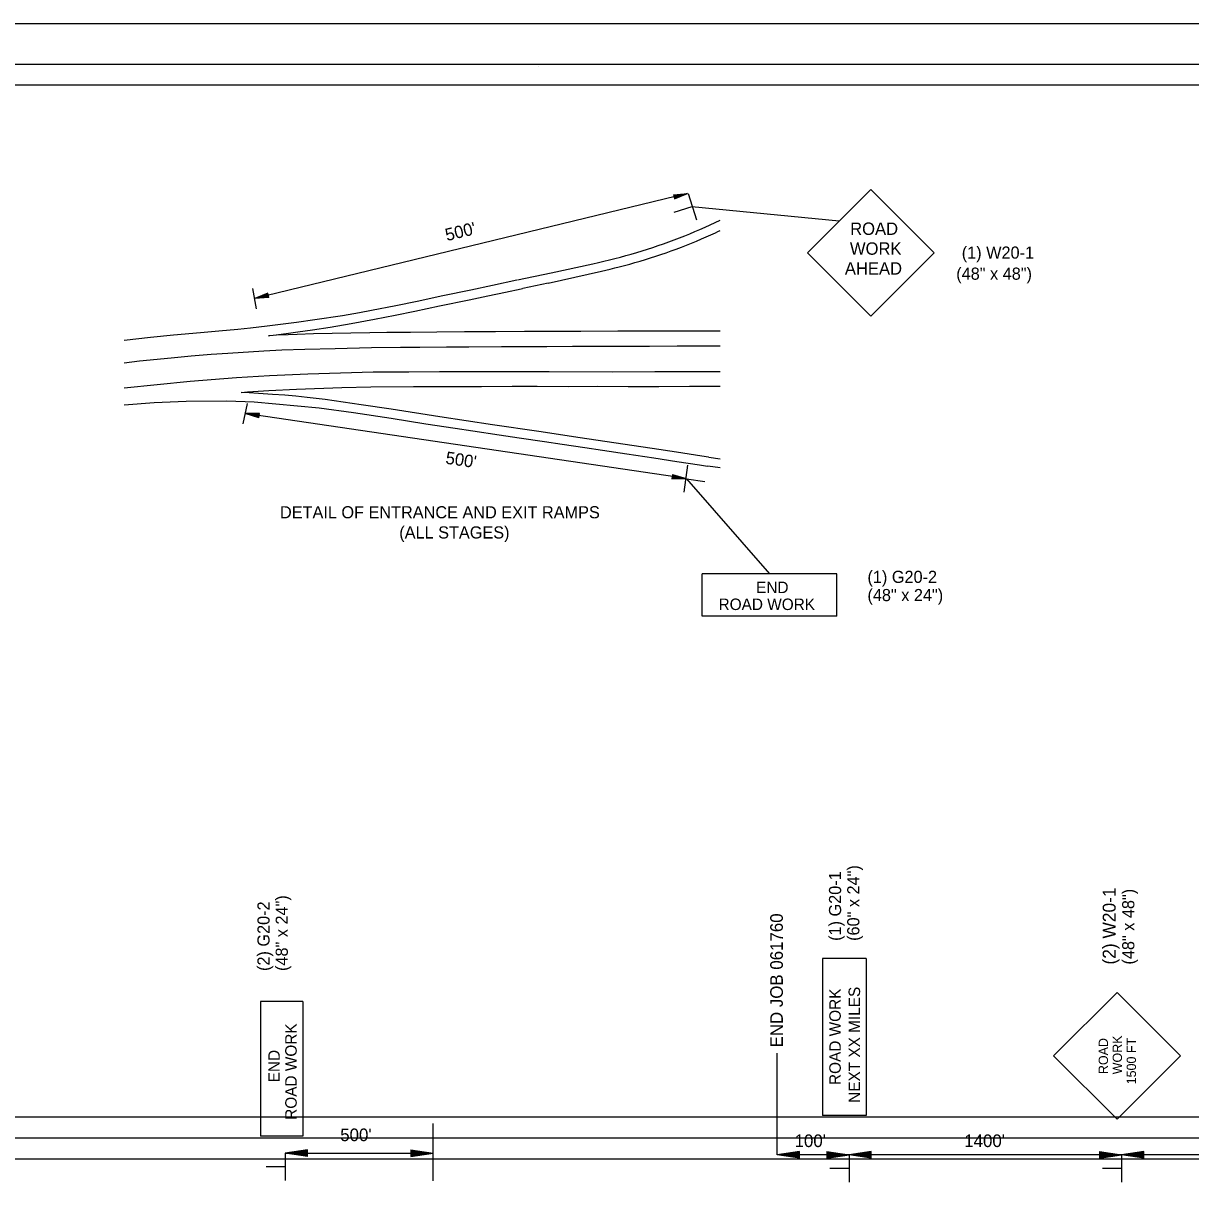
# Model space of a CAD drawing. Extents: x -500 to 213, y 382723 to 382830.
# Drawn here: x -442.4 to -386.5, y 382774.3 to 382829.8 of the extents above; entities that cross this region are included whole.
import ezdxf

# ---------------------------------------------------------------- set-up
doc = ezdxf.new("R2010")
doc.units = 0
for name, color, linetype in [('Default', 7, 'Continuous'), ('R_Border', 7, 'Continuous'), ('R_Border Plan-Plan', 7, 'Continuous'), ('R_Detour', 7, 'Continuous'), ('R_Draft', 7, 'Continuous'), ('R_MOT', 7, 'Continuous'), ('R_No Plot', 7, 'Continuous')]:
    doc.layers.add(name, color=color, linetype=linetype)

msp = doc.modelspace()

# ---------------------------------------------------------------- linework, layer by layer
at = {"layer": 'Default'}
for p, q in [((-403.358, 382820.332), (-410.403, 382821.028)), ((-410.66, 382808.014), (-406.683, 382803.472)), ((-406.313, 382775.68), (-406.313, 382780.536)), ((-422.773, 382774.434), (-422.773, 382777.171)), ((-429.838, 382775.757), (-422.775, 382775.757)), ((-402.883, 382775.68), (-406.313, 382775.68)), ((-389.854, 382775.68), (-402.883, 382775.68)), ((-380.757, 382775.68), (-389.854, 382775.68))]:
    msp.add_line(p, q, dxfattribs=at)
for points in [[(-418.736, 382817.53), (-417.12, 382817.87), (-415.135, 382818.302)], [(-437.544, 382814.647), (-436.29, 382814.788), (-435.182, 382814.895), (-433.892, 382815.008), (-433.019, 382815.086), (-432.105, 382815.177), (-431.51, 382815.241), (-430.701, 382815.334), (-429.298, 382815.51), (-428.426, 382815.627), (-427.104, 382815.83), (-426.289, 382815.968), (-425.71, 382816.081), (-424.552, 382816.304), (-423.533, 382816.517), (-422.3, 382816.774), (-420.965, 382817.054), (-419.937, 382817.276), (-418.765, 382817.522)], [(-417.273, 382817.376), (-418.476, 382817.122)], [(-409.045, 382815.08), (-409.589, 382815.08), (-411.228, 382815.075), (-412.482, 382815.072), (-413.933, 382815.07), (-415.709, 382815.063), (-417.031, 382815.059), (-418.402, 382815.056), (-419.784, 382815.048), (-421.276, 382815.035), (-422.597, 382815.029), (-423.847, 382815.015), (-424.985, 382815.004), (-425.8, 382814.997), (-426.699, 382814.984), (-427.598, 382814.968), (-428.49, 382814.942), (-429.267, 382814.916), (-429.695, 382814.899), (-430.268, 382814.876), (-430.571, 382814.858), (-430.646, 382814.857), (-430.577, 382814.868), (-430.276, 382814.903), (-429.691, 382814.978), (-429.243, 382815.037), (-428.537, 382815.141), (-427.693, 382815.271), (-426.692, 382815.434), (-425.567, 382815.642), (-424.593, 382815.835), (-423.65, 382816.033), (-422.468, 382816.282), (-421.049, 382816.579), (-420.156, 382816.765), (-419.316, 382816.942), (-418.558, 382817.103), (-418.501, 382817.119)], [(-437.544, 382813.563), (-436.816, 382813.648), (-435.302, 382813.802), (-434.342, 382813.895), (-433.377, 382813.971), (-432.592, 382814.027), (-430.87, 382814.136), (-430.005, 382814.174), (-428.905, 382814.211), (-427.457, 382814.251), (-425.721, 382814.287), (-424.327, 382814.305), (-423.408, 382814.312), (-422.136, 382814.321), (-421.058, 382814.328), (-419.507, 382814.335), (-418.42, 382814.34), (-417.332, 382814.346), (-416.108, 382814.351), (-414.413, 382814.356), (-412.427, 382814.361), (-411.101, 382814.366), (-409.647, 382814.368), (-409.045, 382814.368)], [(-437.544, 382812.368), (-434.386, 382812.678), (-432.18, 382812.851), (-430.589, 382812.951), (-428.76, 382813.036), (-425.632, 382813.122), (-423.934, 382813.136), (-422.459, 382813.143), (-419.938, 382813.141), (-417.224, 382813.14), (-414.198, 382813.135), (-412.168, 382813.138), (-410.511, 382813.142), (-409.045, 382813.143)], [(-409.597, 382809.05), (-409.93, 382809.102), (-411.14, 382809.286), (-412.298, 382809.463), (-414.126, 382809.735), (-415.733, 382809.973), (-417.719, 382810.273), (-419.928, 382810.596), (-422.443, 382810.982), (-424.781, 382811.348), (-426.219, 382811.554), (-427.939, 382811.811), (-428.788, 382811.907), (-429.334, 382811.96), (-429.863, 382812.006), (-430.45, 382812.051), (-431.569, 382812.122), (-431.946, 382812.141), (-431.951, 382812.148), (-431.64, 382812.175), (-430.621, 382812.235), (-429.309, 382812.299), (-427.133, 382812.386), (-425.754, 382812.413), (-423.702, 382812.424), (-422.078, 382812.424), (-420.464, 382812.427), (-418.991, 382812.436), (-417.798, 382812.437), (-416.314, 382812.434), (-414.934, 382812.436), (-413.442, 382812.43), (-411.975, 382812.429), (-410.509, 382812.436), (-409.218, 382812.437), (-409.045, 382812.438)], [(-437.544, 382811.547), (-436.115, 382811.669), (-434.58, 382811.733), (-432.628, 382811.744), (-431.322, 382811.702), (-428.216, 382811.41), (-426.584, 382811.179), (-424.777, 382810.906), (-423.117, 382810.648), (-421.714, 382810.434), (-420.878, 382810.303), (-419.614, 382810.11), (-418.651, 382809.975), (-417.453, 382809.796), (-416.593, 382809.667), (-415.523, 382809.507), (-414.68, 382809.38), (-413.515, 382809.202), (-412.224, 382809.01), (-411.111, 382808.843), (-410.038, 382808.68), (-409.659, 382808.624)], [(-409.586, 382809.048), (-409.045, 382808.965)], [(-409.045, 382808.53), (-409.642, 382808.619)]]:
    msp.add_lwpolyline(points, dxfattribs=at)
for centre, major_axis, ratio, start_param, end_param in [((-423.101, 382850.023), (13.67, 29.837), 0.999173, 3.949784, 4.014407), ((-422.295, 382848.064), (31.169, 0.376), 0.99865, 5.108014, 5.139342), ((-420.612, 382844.147), (26.163, 4.854), 0.992861, 4.737589, 4.90036), ((-420.215, 382843.153), (25.787, 2.344), 0.996093, 4.869476, 5.030314), ((-437.119, 382911.522), (96.683, 14.944), 0.983429, 4.765892, 4.801526)]:
    msp.add_ellipse(centre, major_axis=major_axis, ratio=ratio, start_param=start_param, end_param=end_param, dxfattribs=at)
at = {"layer": 'R_Border'}
for p, q in [((-493.998, 382827.85), (-335.908, 382827.85)), ((-417.738, 382827.72), (-417.738, 382827.72)), ((-417.738, 382827.72), (-417.738, 382827.72))]:
    msp.add_line(p, q, dxfattribs=at)
at = {"layer": 'R_Border Plan-Plan'}
msp.add_line((-493.998, 382776.485), (-335.908, 382776.485), dxfattribs=at)
at = {"layer": 'R_Detour'}
for p, q in [((-404.157, 382785.063), (-404.157, 382777.559)), ((-402.071, 382785.063), (-404.157, 382785.063)), ((-402.071, 382785.063), (-402.071, 382777.559)), ((-402.071, 382777.559), (-404.157, 382777.559))]:
    msp.add_line(p, q, dxfattribs=at)
at = {"layer": 'R_Draft'}
for p, q in [((-428.778, 382775.916), (-429.838, 382775.757)), ((-428.778, 382775.598), (-429.838, 382775.757)), ((-428.778, 382775.889), (-429.661, 382775.757)), ((-428.778, 382775.625), (-429.661, 382775.757)), ((-428.778, 382775.862), (-429.478, 382775.757)), ((-428.778, 382775.652), (-429.478, 382775.757)), ((-428.778, 382775.836), (-429.302, 382775.757)), ((-428.778, 382775.678), (-429.302, 382775.757)), ((-428.778, 382775.809), (-429.122, 382775.757)), ((-428.778, 382775.706), (-429.122, 382775.757)), ((-428.778, 382775.782), (-428.946, 382775.757)), ((-428.778, 382775.732), (-428.946, 382775.757)), ((-428.778, 382775.598), (-428.778, 382775.916)), ((-423.834, 382775.916), (-422.775, 382775.757)), ((-423.834, 382775.916), (-423.834, 382775.598)), ((-423.834, 382775.889), (-422.952, 382775.757)), ((-423.834, 382775.862), (-423.134, 382775.757)), ((-423.834, 382775.836), (-423.31, 382775.757)), ((-423.834, 382775.808), (-423.49, 382775.757)), ((-423.834, 382775.782), (-423.667, 382775.757)), ((-423.834, 382775.598), (-422.775, 382775.757)), ((-423.834, 382775.705), (-423.49, 382775.757)), ((-423.834, 382775.652), (-423.134, 382775.757)), ((-423.834, 382775.625), (-422.952, 382775.757)), ((-423.834, 382775.678), (-423.31, 382775.757)), ((-423.834, 382775.732), (-423.667, 382775.757)), ((-405.254, 382775.839), (-406.313, 382775.68)), ((-405.254, 382775.521), (-406.313, 382775.68)), ((-405.254, 382775.813), (-406.136, 382775.68)), ((-405.254, 382775.548), (-406.136, 382775.68)), ((-405.254, 382775.786), (-405.954, 382775.68)), ((-405.254, 382775.575), (-405.954, 382775.68)), ((-405.254, 382775.759), (-405.777, 382775.68)), ((-405.254, 382775.601), (-405.777, 382775.68)), ((-405.254, 382775.732), (-405.598, 382775.68)), ((-405.254, 382775.629), (-405.598, 382775.68)), ((-405.254, 382775.705), (-405.421, 382775.68)), ((-405.254, 382775.656), (-405.421, 382775.68)), ((-405.254, 382775.521), (-405.254, 382775.839)), ((-403.942, 382775.839), (-402.883, 382775.68)), ((-403.942, 382775.839), (-403.942, 382775.521)), ((-403.942, 382775.813), (-403.06, 382775.68)), ((-403.942, 382775.786), (-403.242, 382775.68)), ((-403.942, 382775.759), (-403.418, 382775.68)), ((-403.942, 382775.732), (-403.598, 382775.68)), ((-403.942, 382775.705), (-403.775, 382775.68)), ((-403.942, 382775.521), (-402.883, 382775.68)), ((-403.942, 382775.628), (-403.598, 382775.68)), ((-403.942, 382775.575), (-403.242, 382775.68)), ((-403.942, 382775.548), (-403.06, 382775.68)), ((-403.942, 382775.601), (-403.418, 382775.68)), ((-403.942, 382775.656), (-403.775, 382775.68)), ((-401.823, 382775.839), (-402.883, 382775.68)), ((-401.823, 382775.521), (-402.883, 382775.68)), ((-401.823, 382775.813), (-402.706, 382775.68)), ((-401.823, 382775.548), (-402.706, 382775.68)), ((-401.823, 382775.786), (-402.524, 382775.68)), ((-401.823, 382775.575), (-402.524, 382775.68)), ((-401.823, 382775.759), (-402.347, 382775.68)), ((-401.823, 382775.601), (-402.347, 382775.68)), ((-401.823, 382775.732), (-402.168, 382775.68)), ((-401.823, 382775.629), (-402.168, 382775.68)), ((-401.823, 382775.705), (-401.991, 382775.68)), ((-401.823, 382775.656), (-401.991, 382775.68)), ((-401.823, 382775.521), (-401.823, 382775.839)), ((-390.913, 382775.839), (-389.854, 382775.68)), ((-390.913, 382775.839), (-390.913, 382775.521)), ((-390.913, 382775.813), (-390.031, 382775.68)), ((-390.913, 382775.786), (-390.213, 382775.68)), ((-390.913, 382775.759), (-390.389, 382775.68)), ((-390.913, 382775.732), (-390.569, 382775.68)), ((-390.913, 382775.705), (-390.746, 382775.68)), ((-390.913, 382775.521), (-389.854, 382775.68)), ((-390.913, 382775.628), (-390.569, 382775.68)), ((-390.913, 382775.575), (-390.213, 382775.68)), ((-390.913, 382775.548), (-390.031, 382775.68)), ((-390.913, 382775.601), (-390.389, 382775.68)), ((-390.913, 382775.656), (-390.746, 382775.68)), ((-388.794, 382775.839), (-389.854, 382775.68)), ((-388.794, 382775.521), (-389.854, 382775.68)), ((-388.794, 382775.813), (-389.677, 382775.68)), ((-388.794, 382775.548), (-389.677, 382775.68)), ((-388.794, 382775.786), (-389.494, 382775.68)), ((-388.794, 382775.575), (-389.494, 382775.68)), ((-388.794, 382775.759), (-389.318, 382775.68)), ((-388.794, 382775.601), (-389.318, 382775.68)), ((-388.794, 382775.732), (-389.138, 382775.68)), ((-388.794, 382775.629), (-389.138, 382775.68)), ((-388.794, 382775.705), (-388.962, 382775.68)), ((-388.794, 382775.656), (-388.962, 382775.68)), ((-388.794, 382775.521), (-388.794, 382775.839))]:
    msp.add_line(p, q, dxfattribs=at)
at = {"layer": 'R_MOT'}
for p, q in [((-404.873, 382818.817), (-401.843, 382821.848)), ((-401.843, 382821.848), (-398.812, 382818.817)), ((-410.602, 382821.657), (-431.304, 382816.631)), ((-411.274, 382821.597), (-410.602, 382821.657)), ((-411.274, 382821.597), (-411.227, 382821.402)), ((-411.27, 382821.58), (-410.71, 382821.63)), ((-411.266, 382821.564), (-410.822, 382821.603)), ((-411.262, 382821.548), (-410.93, 382821.577)), ((-411.258, 382821.531), (-411.04, 382821.55)), ((-411.254, 382821.514), (-411.148, 382821.524)), ((-411.247, 382821.484), (-411.148, 382821.524)), ((-411.243, 382821.467), (-411.04, 382821.55)), ((-411.239, 382821.451), (-410.93, 382821.577)), ((-411.235, 382821.435), (-410.822, 382821.603)), ((-411.231, 382821.418), (-410.71, 382821.63)), ((-411.227, 382821.402), (-410.602, 382821.657)), ((-410.583, 382821.654), (-410.184, 382820.407)), ((-410.403, 382821.028), (-411.254, 382820.756)), ((-404.873, 382818.817), (-401.843, 382815.789)), ((-401.843, 382815.789), (-398.812, 382818.817)), ((-431.216, 382816.144), (-431.392, 382817.117)), ((-430.679, 382816.885), (-431.304, 382816.631)), ((-430.675, 382816.869), (-431.196, 382816.657)), ((-430.671, 382816.853), (-431.084, 382816.684)), ((-430.667, 382816.836), (-430.976, 382816.71)), ((-430.663, 382816.82), (-430.866, 382816.737)), ((-430.648, 382816.757), (-430.866, 382816.737)), ((-430.659, 382816.803), (-430.758, 382816.763)), ((-430.652, 382816.773), (-430.758, 382816.763)), ((-430.632, 382816.691), (-430.679, 382816.885)), ((-430.632, 382816.691), (-431.304, 382816.631)), ((-430.636, 382816.707), (-431.196, 382816.657)), ((-430.64, 382816.723), (-431.084, 382816.684)), ((-430.644, 382816.74), (-430.976, 382816.71)), ((-431.855, 382810.647), (-431.653, 382811.615)), ((-431.079, 382811.132), (-431.754, 382811.131)), ((-410.679, 382808.02), (-431.754, 382811.131)), ((-431.108, 382810.934), (-431.754, 382811.131)), ((-431.082, 382811.116), (-431.644, 382811.115)), ((-431.106, 382810.951), (-431.644, 382811.115)), ((-431.084, 382811.099), (-431.53, 382811.098)), ((-431.104, 382810.968), (-431.53, 382811.098)), ((-431.087, 382811.083), (-431.42, 382811.082)), ((-431.101, 382810.984), (-431.42, 382811.082)), ((-431.089, 382811.066), (-431.308, 382811.065)), ((-431.099, 382811.001), (-431.308, 382811.065)), ((-431.092, 382811.049), (-431.198, 382811.049)), ((-431.096, 382811.018), (-431.198, 382811.049)), ((-431.108, 382810.934), (-431.079, 382811.132)), ((-410.772, 382807.372), (-410.586, 382808.667)), ((-411.325, 382808.216), (-411.354, 382808.018)), ((-411.354, 382808.018), (-410.679, 382808.02)), ((-411.351, 382808.035), (-410.789, 382808.036)), ((-411.349, 382808.051), (-410.903, 382808.053)), ((-411.346, 382808.068), (-411.013, 382808.069)), ((-411.344, 382808.085), (-411.125, 382808.085)), ((-411.341, 382808.102), (-411.235, 382808.102)), ((-411.337, 382808.133), (-411.235, 382808.102)), ((-411.334, 382808.149), (-411.125, 382808.085)), ((-411.332, 382808.166), (-411.013, 382808.069)), ((-411.329, 382808.183), (-410.903, 382808.053)), ((-411.327, 382808.2), (-410.789, 382808.036)), ((-411.325, 382808.216), (-410.679, 382808.02)), ((-410.66, 382808.014), (-409.776, 382807.887)), ((-403.464, 382803.472), (-409.901, 382803.472)), ((-409.901, 382801.449), (-409.901, 382803.472)), ((-403.464, 382801.449), (-403.464, 382803.472)), ((-403.464, 382801.449), (-409.901, 382801.449)), ((-390.07, 382783.445), (-393.101, 382780.415)), ((-390.07, 382783.445), (-387.042, 382780.415)), ((-431.03, 382783.01), (-431.03, 382776.573)), ((-429.007, 382783.01), (-431.03, 382783.01)), ((-429.007, 382783.01), (-429.007, 382776.573)), ((-393.101, 382780.415), (-390.07, 382777.384)), ((-387.042, 382780.415), (-390.07, 382777.384)), ((-429.007, 382776.573), (-431.03, 382776.573)), ((-429.838, 382775.757), (-429.838, 382774.448)), ((-402.883, 382775.68), (-402.883, 382774.371)), ((-389.854, 382775.68), (-389.854, 382774.371)), ((-429.857, 382775.106), (-430.75, 382775.106)), ((-402.902, 382775.029), (-403.795, 382775.029)), ((-389.873, 382775.029), (-390.766, 382775.029))]:
    msp.add_line(p, q, dxfattribs=at)
at = {"layer": 'R_No Plot'}
for points in [[(-500.202, 382829.798), (-333.532, 382829.798), (-333.532, 382723.129), (-500.202, 382723.129)], [(-336.908, 382777.485), (-492.998, 382777.485), (-492.998, 382826.85), (-368.228, 382826.85), (-368.228, 382821.91), (-359.458, 382821.91), (-347.408, 382821.91), (-347.408, 382810.744), (-336.908, 382810.744)], [(-492.998, 382826.85), (-368.228, 382826.85), (-368.228, 382821.91), (-359.458, 382821.91), (-347.408, 382821.91), (-347.408, 382810.744), (-336.908, 382810.744), (-336.908, 382726.12), (-492.998, 382726.12)], [(-492.998, 382775.485), (-336.908, 382775.485), (-336.908, 382726.12), (-492.998, 382726.12)]]:
    msp.add_lwpolyline(points, close=True, dxfattribs=at)

# ---------------------------------------------------------------- texts
at = {"layer": 'Default'}
for s, height, p in [('DETAIL OF ENTRANCE AND EXIT RAMPS', 0.5814, (-430.094, 382806.122)), ('(ALL STAGES)', 0.5814, (-424.389, 382805.157)), ("500'", 0.6031, (-427.213, 382776.333)), ("100'", 0.6031, (-405.487, 382776.05)), ("1400'", 0.6031, (-397.375, 382776.05))]:
    msp.add_text(s, height=height, dxfattribs=at).set_placement(p)
msp.add_text('END JOB 061760', height=0.60315, rotation=90, dxfattribs=at).set_placement((-406.048, 382780.814))
at = {"layer": 'R_MOT'}
for s, height, rotation, p in [("500'", 0.5933, 13.6464, (-422.113, 382819.378)), ('ROAD', 0.5933, 359.9996, (-402.831, 382819.678)), ('WORK', 0.5933, 359.9996, (-402.842, 382818.729)), ('(1) W20-1', 0.5815, 360, (-397.494, 382818.542)), ('AHEAD', 0.5933, 359.9996, (-403.083, 382817.779)), ('(48" x 48")', 0.58146, 360, (-397.757, 382817.535)), ("500'", 0.5933, 351.6023, (-422.204, 382808.738)), ('(60" x 24")', 0.5814, 90, (-402.39, 382785.911)), ('(1) G20-1', 0.5815, 90, (-403.262, 382785.911)), ('(2) W20-1', 0.6202, 90, (-390.135, 382784.779)), ('(48" x 48")', 0.5814, 90, (-389.242, 382784.779)), ('(2) G20-2', 0.5815, 90, (-430.591, 382784.471)), ('(48" x 24")', 0.5814, 90, (-429.719, 382784.471)), ('ROAD WORK', 0.5495, 90, (-403.278, 382779.017)), ('NEXT XX MILES', 0.54947, 90, (-402.356, 382778.165)), ('ROAD WORK', 0.5495, 90, (-429.293, 382777.352)), ('ROAD', 0.4465, 90.0004, (-390.502, 382779.539)), ('WORK', 0.4464, 90, (-389.832, 382779.53)), ('1500 FT', 0.4465, 90.0006, (-389.163, 382779.049)), ('END', 0.5495, 90, (-430.104, 382779.145))]:
    msp.add_text(s, height=height, rotation=rotation, dxfattribs=at).set_placement(p)
for s, height, p in [('(1) G20-2', 0.5815, (-402.003, 382803.033)), ('END', 0.5495, (-407.328, 382802.546)), ('ROAD WORK', 0.5495, (-409.122, 382801.735)), ('(48" x 24")', 0.5814, (-402.003, 382802.161))]:
    msp.add_text(s, height=height, dxfattribs=at).set_placement(p)

doc.saveas('drawing.dxf')
